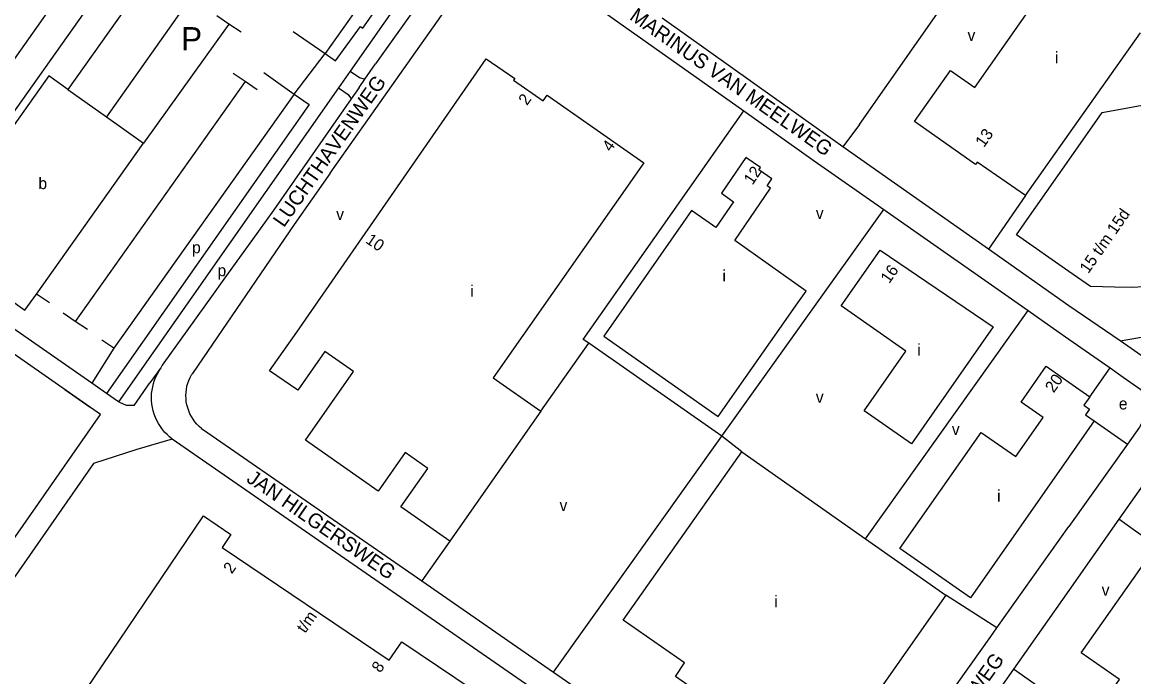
# Model space of a CAD drawing. Extents: x 154765 to 156627, y 383996 to 386132.
# Drawn here: x 155041.5 to 155422.2, y 384927.3 to 385151.6 of the extents above; entities that cross this region are included whole.
import ezdxf

# ---------------------------------------------------------------- set-up
doc = ezdxf.new("R2010")
doc.units = 0
for name, color, linetype in [('BLT_Basislijn', 7, 'Continuous'), ('BLT_Bebouwing', 7, 'Continuous'), ('BLT_Centroide', 7, 'Continuous'), ('BLT_Huisnummer', 7, 'Continuous'), ('BLT_Huisnummer_reeks', 7, 'Continuous'), ('BLT_Straatnaam', 7, 'Continuous'), ('BLT_Tekst_parkeren', 7, 'Continuous')]:
    doc.layers.add(name, color=color, linetype=linetype)

msp = doc.modelspace()

# ---------------------------------------------------------------- linework, layer by layer
at = {"layer": 'BLT_Basislijn'}
for p, q in [((155223.98, 385234.96), (155153.88, 385134.89)), ((155328.26, 385116.57), (155393.24, 385209.32)), ((155170.21, 385176.26), (155145.22, 385140.85)), ((155086.01, 385169.34), (155057.14, 385128.56)), ((155099.3, 385160.16), (155070.32, 385119.22)), ((155112.33, 385150.97), (155108.19, 385153.78)), ((155322.62, 385108.95), (155260.74, 385153.01)), ((155112.33, 385150.97), (155083.08, 385110.17)), ((155116.47, 385148.17), (155112.33, 385150.97)), ((155134.27, 385148.4), (155145.22, 385140.85)), ((155134.65, 385126.99), (155145.22, 385140.85)), ((155158.88, 385132.16), (155162.53, 385137.4)), ((155117.89, 385131.29), (155113.75, 385134.09)), ((155124.29, 385134.42), (155134.65, 385126.99)), ((155153.88, 385134.89), (155149.84, 385129.13)), ((155117.89, 385131.29), (155059.7, 385049.11)), ((155149.84, 385129.13), (155074.49, 385021.56)), ((155122.03, 385128.49), (155117.89, 385131.29)), ((155156.87, 385129.27), (155154.13, 385125.35)), ((155156.87, 385129.27), (155158.88, 385132.16)), ((155134.65, 385126.99), (155072.91, 385039.88)), ((155154.13, 385125.35), (155127.65, 385087.35)), ((155233.61, 385042.94), (155288.69, 385121.24)), ((155328.26, 385116.57), (155322.62, 385108.95)), ((155385.16, 385092.22), (155372.45, 385073.82)), ((155281.16, 385009.75), (155336.6, 385087.49)), ((155336.6, 385087.49), (155386.05, 385052.79)), ((155122.42, 385080.05), (155110.01, 385062.76)), ((155400, 385054.46), (155372.45, 385073.82)), ((155065.31, 385027.95), (155003.26, 385071.14)), ((155110.01, 385062.76), (155106.9, 385058.42)), ((155050.81, 385055.43), (155046.36, 385058.44)), ((155330.39, 384974.6), (155386.05, 385052.79)), ((155386.05, 385052.79), (155391.53, 385048.95)), ((155059.7, 385049.11), (155055.56, 385051.91)), ((155063.84, 385046.3), (155059.7, 385049.11)), ((155391.53, 385048.95), (155400, 385043.01)), ((155417.54, 385042.4), (155453.37, 385048.72)), ((155072.91, 385039.88), (155068.77, 385042.68)), ((155219.18, 385018.32), (155235.53, 385041.6)), ((155235.53, 385041.6), (155233.61, 385042.94)), ((155281.16, 385009.75), (155235.53, 385041.6)), ((155072.91, 385039.88), (155065.31, 385027.95)), ((155089.02, 385033.16), (155085.26, 385028.08)), ((155100.04, 385031.65), (155099.66, 385031.08)), ((155407.2, 385023.27), (155414.13, 385033.17)), ((155070.38, 385024.42), (155065.31, 385027.95)), ((155079.83, 385020.3), (155085.26, 385028.08)), ((155056.16, 385025.78), (155064.82, 385019.73)), ((155074.49, 385021.56), (155070.38, 385024.42)), ((155408.67, 385014.99), (155420.04, 385007.04)), ((155229.24, 384914.38), (155092.91, 385008.79)), ((155223.52, 384928.91), (155281.16, 385009.75)), ((155287.95, 385004.43), (155281.16, 385009.75)), ((155065.97, 385000.42), (155021.15, 384936.15)), ((155422.86, 384977.28), (155417.1, 384981.32)), ((155375.29, 384944.07), (155400, 384978.84)), ((155187.95, 384973.83), (155178.37, 384960.17)), ((155375.29, 384944.07), (155357.91, 384955.27)), ((155373.23, 384941.17), (155375.29, 384944.07)), ((155399.36, 384917.11), (155381.05, 384929.95))]:
    msp.add_line(p, q, dxfattribs=at)
for points in [[(155234.74, 385412.07), (155228.58, 385403.41), (155224.55, 385391.47), (155216.21, 385379.72), (155192.97, 385359.25), (155123.67, 385259.51), (155043.61, 385145.9), (155014.37, 385104.41), (155012.61, 385102.8), (155010.41, 385101.87), (155008.28, 385101.81), (155005.41, 385102.5), (155003.02, 385104.02), (155002.04, 385105.22), (155001.66, 385106.08), (155001.51, 385106.85), (155001.53, 385107.93)], [(155145.22, 385140.85), (155148.83, 385138.37), (155157.37, 385150.17), (155158.23, 385149.59), (155211.18, 385225.29), (155210.33, 385226.16)], [(155108.39, 385219.41), (155090.89, 385194.93), (155003.26, 385071.14)], [(155147, 385099.88), (155189.27, 385159.89), (155197.12, 385171.44), (155200.67, 385174.74), (155205.13, 385176.33), (155209.65, 385176.09), (155212.87, 385174.9), (155288.69, 385121.24)], [(155183.52, 385166.98), (155164.42, 385140.11), (155162.53, 385137.4)], [(155153.88, 385134.89), (155157.03, 385132.71), (155158.88, 385132.16)], [(155149.84, 385129.13), (155153.15, 385126.84), (155154.13, 385125.35)], [(155134.65, 385126.99), (155139.74, 385123.43), (155070.38, 385024.42)], [(155288.69, 385121.24), (155312.8, 385104.18), (155336.6, 385087.49)], [(155372.45, 385073.82), (155334.89, 385100.21), (155322.62, 385108.95)], [(155147, 385099.88), (155134.65, 385082.34), (155100.04, 385031.65)], [(155127.65, 385087.35), (155122.42, 385080.05)], [(155106.9, 385058.42), (155089.46, 385034.11), (155089.02, 385033.16)], [(155417.54, 385042.4), (155400, 385054.46)], [(155400, 385043.01), (155414.13, 385033.17)], [(155426.24, 385036.42), (155417.54, 385042.4)], [(155086.01, 385020.23), (155085.92, 385020.79), (155085.82, 385021.97), (155085.79, 385023.16), (155085.84, 385024.35), (155085.97, 385025.53), (155086.19, 385026.7), (155086.48, 385027.85), (155086.84, 385028.99), (155087.29, 385030.09), (155087.8, 385031.16), (155088.39, 385032.2), (155089.02, 385033.16)], [(155102.92, 385012.42), (155102.11, 385013.13), (155101.36, 385013.89), (155100.66, 385014.71), (155100.03, 385015.57), (155099.46, 385016.49), (155098.97, 385017.44), (155098.54, 385018.42), (155098.19, 385019.44), (155097.92, 385020.47), (155097.72, 385021.53), (155097.61, 385022.6), (155097.57, 385023.67), (155097.62, 385024.74), (155097.74, 385025.81), (155097.94, 385026.86), (155098.22, 385027.9), (155098.58, 385028.91), (155099.01, 385029.89), (155099.51, 385030.84), (155099.66, 385031.08)], [(155414.13, 385033.17), (155418.65, 385030.02), (155424.69, 385025.76), (155426.85, 385020.91), (155426.31, 385017.14), (155424.15, 385012.83), (155420.04, 385007.04)], [(155079.83, 385020.3), (155077.28, 385020.3), (155074.9, 385021.27), (155074.49, 385021.56)], [(155092.91, 385008.79), (155091.98, 385009.53), (155091.1, 385010.33), (155090.28, 385011.19), (155089.52, 385012.1), (155088.82, 385013.07), (155088.19, 385014.07), (155087.62, 385015.12), (155087.13, 385016.2), (155086.72, 385017.32), (155086.37, 385018.46), (155086.11, 385019.61), (155086.01, 385020.23)], [(155102.92, 385012.42), (155105.09, 385010.91), (155178.37, 384960.17)], [(155092.91, 385008.79), (155080.8, 385005.26), (155065.97, 385000.42)], [(155420.04, 385007.04), (155400, 384978.84)], [(155451.34, 385007.42), (155450.54, 385007.98), (155444.62, 385009.6), (155438.7, 385009.06), (155434.39, 385005.82), (155417.1, 384981.32)], [(155417.1, 384981.32), (155400, 384956.91)], [(155178.37, 384960.17), (155223.52, 384928.91)], [(155400, 384956.91), (155381.05, 384929.95)], [(155223.52, 384928.91), (155309.72, 384869.23), (155312.41, 384868.15), (155317.26, 384867.61), (155323.45, 384871.11), (155373.23, 384941.17)], [(155381.05, 384929.95), (155334.76, 384864.11), (155333.42, 384860.6), (155335.57, 384856.29), (155338.8, 384850.37), (155400, 384807.65)]]:
    msp.add_lwpolyline(points, dxfattribs=at)
at = {"layer": 'BLT_Bebouwing'}
for p, q in [((155400, 385113.29), (155424.54, 385148.02)), ((155057.14, 385128.56), (155070.32, 385119.22)), ((155070.32, 385119.22), (155083.08, 385110.17)), ((155046.36, 385058.44), (155083.08, 385110.17)), ((155385.16, 385092.22), (155400, 385113.29)), ((155287.95, 385004.43), (155330.39, 384974.6)), ((155059.18, 384916.85), (155103.58, 384982.45)), ((155330.39, 384974.6), (155357.91, 384955.27)), ((155167.2, 384933.01), (155171.49, 384939.33)), ((155171.49, 384939.33), (155201.86, 384918.83))]:
    msp.add_line(p, q, dxfattribs=at)
for points in [[(155385.16, 385092.22), (155368.63, 385103.71), (155368.07, 385102.91), (155347.16, 385117.55), (155359.43, 385135.08), (155367.77, 385129.25), (155400, 385175.33)], [(155187.95, 384973.83), (155171.24, 384985.52), (155180.48, 384998.69), (155172.66, 385004.16), (155163.45, 384990.99), (155138.55, 385008.43), (155155.03, 385031.91), (155145.13, 385038.83), (155135.88, 385025.58), (155126.22, 385032.2), (155135.55, 385045.47), (155200.41, 385139.11), (155210.21, 385132.38), (155209.76, 385131.74), (155219.94, 385124.63), (155221.35, 385126.65), (155254.39, 385103.49), (155202.8, 385029.79)], [(155057.14, 385128.56), (155050.59, 385133.21), (155012.92, 385080.15), (155019.1, 385075.56), (155019.4, 385075.98), (155022.81, 385073.57), (155019.67, 385069.15), (155042.45, 385052.95), (155046.36, 385058.44)], [(155400, 385104.36), (155411.43, 385120.68), (155432.67, 385124.51), (155438.05, 385132.17), (155467.8, 385111.44), (155471.9, 385108.58), (155466.59, 385100.99), (155474.93, 385095.15), (155457.22, 385069.83), (155449.21, 385066.66), (155444.34, 385064.78), (155439.85, 385063.36), (155435.29, 385062.31), (155430.51, 385061.49), (155425.98, 385060.94), (155421.34, 385060.7), (155415.6, 385060.82), (155407.39, 385061.04), (155400, 385066.22)], [(155307.14, 385055.43), (155310.02, 385059.52), (155285.54, 385076.77), (155297.85, 385094.72), (155296.65, 385095.58), (155298.22, 385097.96), (155293.86, 385101.05), (155294.36, 385101.84), (155289.41, 385105.32), (155281.03, 385093.08), (155285.15, 385090.06), (155279.06, 385081.3), (155270.77, 385087.12), (155267.91, 385083.02), (155240.71, 385044.07), (155279.93, 385016.52), (155307.14, 385055.43)], [(155400, 385066.22), (155382.08, 385078.78), (155384.95, 385082.87), (155400, 385104.36)], [(154989.77, 385071.98), (154939.28, 384999.74), (155017.82, 384944.9), (155068.35, 385017.24), (154989.77, 385071.98)], [(155400, 385002.6), (155366.26, 384954.38), (155342.16, 384971.24), (155370.01, 385011.04), (155381.83, 385002.77), (155391.2, 385016.16), (155383.64, 385021.45), (155392.24, 385033.74), (155400, 385028.31)], [(155202.8, 385029.79), (155219.18, 385018.32)], [(155400, 385028.31), (155407.2, 385023.27)], [(155407.2, 385023.27), (155405.17, 385020.37), (155407.12, 385019), (155405.75, 385017.04), (155408.67, 385014.99)], [(155219.18, 385018.32), (155206.62, 385000.38)], [(155408.67, 385014.99), (155400, 385002.6)], [(155357.91, 384955.27), (155326.66, 384910.93), (155325.53, 384911.73), (155312.84, 384894.01), (155265.22, 384927.44), (155268.31, 384932.07), (155247.39, 384946.75), (155287.95, 385004.43)], [(155206.62, 385000.38), (155187.95, 384973.83)], [(155444.72, 384997.98), (155463.95, 384984.47), (155458.92, 384977.32), (155471.07, 384968.79), (155464.07, 384958.83), (155473.14, 384952.46), (155437.27, 384901.4), (155412.17, 384919.04), (155417.32, 384926.36), (155404.26, 384935.53), (155430.04, 384972.23), (155422.86, 384977.28)], [(155103.58, 384982.45), (155112.96, 384976.06), (155110.04, 384971.64), (155167.2, 384933.01)]]:
    msp.add_lwpolyline(points, dxfattribs=at)
msp.add_lwpolyline([(155346.07, 385007.13), (155329.84, 385018.48), (155344.14, 385038.95), (155322.01, 385054.44), (155335.4, 385073.46), (155374.05, 385047.29)], close=True, dxfattribs=at)

# ---------------------------------------------------------------- texts
at = {"layer": 'BLT_Centroide'}
for s, p in [('v', (155365.29, 385145.23)), ('i', (155395.22, 385137.5)), ('b', (155047.06, 385094.42)), ('v', (155149.05, 385083.88)), ('v', (155313.33, 385084.23)), ('p', (155099.68, 385072.46)), ('p', (155108.41, 385064.58)), ('i', (155281.34, 385062.78)), ('i', (155194.97, 385057.53)), ('i', (155348.03, 385037.42)), ('v', (155313.33, 385021.23)), ('e', (155417.11, 385018.94)), ('v', (155359.92, 385010.18)), ('i', (155375.42, 384987.36)), ('v', (155225.55, 384984.13)), ('v', (155411.24, 384955.11)), ('i', (155299.07, 384951.16))]:
    msp.add_text(s, height=4, dxfattribs=at).set_placement(p)
at = {"layer": 'BLT_Huisnummer'}
for s, rotation, p in [('13', 55.0179, (155370.92, 385108.49)), ('12', 55.5405, (155291.62, 385095.61)), ('16', 55.1348, (155338.46, 385061.83)), ('20', 55.0173, (155394.8, 385024.39))]:
    msp.add_text(s, height=4, rotation=rotation, dxfattribs=at).set_placement(p)
at = {"layer": 'BLT_Huisnummer_reeks'}
for s, rotation, p in [('2', 55.0133, (155214.41, 385122.88)), ('4', 55.0133, (155243.11, 385106.99)), ('15 t/m 15d', 54.993, (155406.64, 385065.23)), ('10', 325.4768, (155158.83, 385076.25)), ('2', 54.9666, (155113.3, 384962.38)), ('t/m', 54.9666, (155138.4, 384942.02)), ('8', 54.9666, (155164.12, 384928.44))]:
    msp.add_text(s, height=4, rotation=rotation, dxfattribs=at).set_placement(p)
at = {"layer": 'BLT_Straatnaam'}
for s, rotation, p in [('MARINUS VAN MEELWEG', 324.9485, (155249.22, 385152.79)), ('LUCHTHAVENWEG', 54.8419, (155131.11, 385081.03)), ('JAN HILGERSWEG', 325.2991, (155117.97, 384994.41)), ('HENRI WIJNMALENWEG', 54.4808, (155332.79, 384869.73))]:
    msp.add_text(s, height=5, rotation=rotation, dxfattribs=at).set_placement(p)
at = {"layer": 'BLT_Tekst_parkeren'}
msp.add_text('P', height=8, rotation=359.9654, dxfattribs=at).set_placement((155095.97, 385141.93))

doc.saveas('drawing.dxf')
